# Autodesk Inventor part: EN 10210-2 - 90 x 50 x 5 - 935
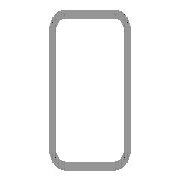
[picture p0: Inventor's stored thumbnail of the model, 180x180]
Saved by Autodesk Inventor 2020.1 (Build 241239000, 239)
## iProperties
Created: 2019-01
Part Number: EN 10210-2 - 90 x 50 x 5 - 935
Material: Stahl, weich
Description: Rohrleitung
Document SubType Name: Modeling
Standard: DIN
Designer: lutzd
Standard Revision: 2006-07
Standards Organization: DIN
Language: de-DE
Size Designation: 90 x 50 x 5
Categories: <MemberInstance><Categories><Category DisplayName="Profile" InternalName="089c4875-fa83-4c05-b084-43b9cc11f5ed" Mnemonic="GRDR"><CategoryParameter DisplayName="
Stock Number: 90 x 50 x 5
Mass: 9344.78 g
Surface Area: 4686.81 cm^2
Volume: 1190.42 cm^3
Density: 7.85 g/cm^3
Appearance: Halbpoliert
IsCustomPart: 1
G_W: 50,000 mm
G_H: 90,000 mm
DocNumber: ADSK-014222
Folder: .
Dimensions: 50x90x935 mm
Mass: 9,345 kg
+2AE981C9-7D38-4FC6-AF2F-C0866793C24F+SCHNITTDETAIL1: Schnittwinkel 90,00 grd
+C03AC384-5E56-4CC7-BDCA-F902E623A23C+SCHNITTDETAIL2: Schnittwinkel 90,00 grd
G_L: 935,000 mm
_CCFamilyMember: 153
_CCFamilyDisplayName: DIN EN 10210-2 (USAS B17.1 rechteckig) - Rohrleitung — In Klammern angegebene Größen wurden aufgehoben
_FrameMemberDoc: Frame Member File
_Version: 15.0.0
_GetPNFromCC: 1
Title: Profil-Bauteil
Author: lutzd
Revision Number: -
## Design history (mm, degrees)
node "Startebene"
node "Endebene"
sketch "Skizze"
  geometry: L1 (-25, -37.5)-(-25, 37.5); L2 (-17.5, 45)-(17.5, 45); L3 (25, 37.5)-(25, -37.5); L4 (17.5, -45)-(-17.5, -45); L5 (-15, 40)-(15, 40); L6 (20, 35)-(20, -35); L7 (15, -40)-(-15, -40); L8 (-20, -35)-(-20, 35); L9 (0, 65.175)-(0, -65.175) reference; L10 (-37.175, 0)-(37.175, 0) reference; A1 r 7.5 centre (-17.5, -37.5) between (-25, -37.5) and (-17.5, -45); A2 r 7.5 centre (-17.5, 37.5) between (-17.5, 45) and (-25, 37.5); A3 r 7.5 centre (17.5, 37.5) between (25, 37.5) and (17.5, 45); A4 r 7.5 centre (17.5, -37.5) between (17.5, -45) and (25, -37.5); A5 r 5 centre (-15, -35) between (-20, -35) and (-15, -40); A6 r 5 centre (-15, 35) between (-15, 40) and (-20, 35); A7 r 5 centre (15, 35) between (20, 35) and (15, 40); A8 r 5 centre (15, -35) between (15, -40) and (20, -35)
  constraints: 16 end point, 16 point on circle, 16 tangent, 8 centre point, 6 equal radius, 4 parallel, 2 perpendicular, 2 other
  dimensions: "d7" = 7.5 radius of A1 (= G_IR); "d10" = 90 distance between parallel lines of L2 L4 (= G_H); "d11" = 50 distance between parallel lines of L1 L3 (= G_W); "d12" = 5 distance between parallel lines of L3 L6 (= G_T); "d15" = 45 distance between parallel lines of L2 L10 (= 0.5 x d10); "d16" = 25 distance between parallel lines of L9 L3 (= 0.5 x d11); "d19" = 5 radius of A5 (= G_T); "d20" = 5 distance between parallel lines of L4 L7 (= G_T)
extrude "Körper" new body sketch "Skizze" stored distance "d3" = 935 (= G_L); taper "d4" = 0 deg
node "Driven Length"
  sketch "Sketch3"
    geometry: L1 (0, 0)-(10, 0) reference
    constraints: 2 end point, 1 horizontal
  workplane "Work Plane3"
  sketch "Sketch4"
    geometry: L1 (-2, 25)-(12, 25) reference; L2 (-2, 960)-(12, 960) reference
    dimensions: "d18" = 935 distance between parallel lines of L1 L2 (derived)
workplane "Arbeitsebene4"
feature "Trennen1"
workplane "Arbeitsebene5"
feature "Trennen2"
body "Solid1"
other parameters: "G_W" = 50 [user parameter; used in 1 equation term], "G_H" = 90 [user parameter; used in 1 equation term], "G_T" = 5 [user parameter; used in 3 equation terms], "G_IR" = 7.5 [user parameter; used in 1 equation term], "G_L" = 935 (= d18) [user parameter; used in 1 equation term], "G_OFFSET_START" = -25 [user parameter; used in 1 equation term], "G_OFFSET_END" = -25 [user parameter; used in 1 equation term], "d13" = 25 (= -G_OFFSET_START), "B_L" = 985 [user parameter; used in 1 equation term], "d17" = 90 deg
